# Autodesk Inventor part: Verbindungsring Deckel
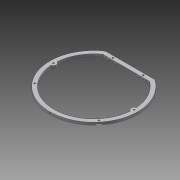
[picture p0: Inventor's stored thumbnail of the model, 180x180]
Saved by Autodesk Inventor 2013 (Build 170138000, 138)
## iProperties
Created: 2012-10
Part Number: Verbindungsring Deckel
Material: Aluminium 6061
Document SubType Name: Modeling
Designer: rYan
Density: 2.71 g/cm^3
Mass: 54.831 g
Surface Area: 139.215 cm^2
Volume: 20.2328 cm^3
Author: rYan
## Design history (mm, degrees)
sketch "Skizze1"
  geometry: L1 (0, 103.8)-(0, -118.8) reference; L2 (-121.8, 0)-(121.8, 0) reference; L3 (-48.836, 72)-(-32.512, 72); L4 (32.512, 72)-(48.836, 72); L5 (-46.314, 64)-(46.314, 64); L6 (-32.512, 72)-(32.512, 72); A1 r 87 centre (0, 0) between (-48.836, 72) and (48.836, 72); A2 r 6 centre (-80, 0) between (-78.781, -5.875) and (-78.781, 5.875); A3 r 6 centre (80, 0) between (78.781, 5.875) and (78.781, -5.875); A4 r 79 centre (0, 0) between (-46.314, 64) and (-78.781, 5.875); A5 r 79 centre (0, 0) between (-78.781, -5.875) and (78.781, -5.875); A6 r 79 centre (0, 0) between (78.781, 5.875) and (46.314, 64); 1 further point
  constraints: 12 point on circle, 8 end point, 6 centre point, 4 parallel, 2 coincident, 2 point on line, 1 symmetric about line
  dimensions: "d0" = 174 diameter of A1; "d4" = 64 distance between parallel lines of L2 L5; "d5" = 8 distance between parallel lines of L6 L5; "d98" = 12 diameter of A2; "d99" = 12 diameter of A3; "d100" = 160 distance of A3.centre A2.centre
extrude "Extrusion1" new body sketch "Skizze1" stored distance "d6" = 5; taper "d7" = 0 deg
workplane "Arbeitsebene6"
workaxis "Arbeitsachse2"
sketch "Skizze10"
  geometry: L1 (-46.314, 64)-(46.314, 64) reference; L2 (48.836, 72)-(-48.836, 72) reference; L3 (0, 0)-(-63.582, -53.351); L4 (0, 0)-(63.582, -53.351); L5 (-121.8, 0)-(121.8, 0) reference; L6 (0, 72)-(0, 64); L7 (-30, 68)-(30, 68); A1 r 87 centre (0, 0) between (-48.836, 72) and (48.836, 72) reference; A2 r 83 centre (0, 0) between (-63.582, -53.351) and (63.582, -53.351); 5 further points
  constraints: 8 end point, 5 coincident, 4 midpoint, 2 point on circle, 1 centre point, 1 perpendicular, 1 symmetric about line
  dimensions: "d77" = 166 diameter of A2; "d78" = 40 deg angle of L3 L5; "d80" = 40 deg angle of L5 L4 (= d78); "d82" = 60 distance of L7.start L7.end
hole "Bohrung6" sketch "Skizze10" at (-63.582, -53.351), (63.582, -53.351), (-30, 68), (30, 68) diameter "d83" = 3.2; stored, may be unused: countersink angle "d87" = 90 deg, drill point angle "d89" = 118 deg; dims "d84" = 6, "d85" = 4, "d86" = 2, "d88" = 8
sketch "Skizze5"
  geometry: 2 further points
  constraints: 1 coincident
hole "Bohrung2" sketch "Skizze5" at (0, 0) diameter "d21" = 2.459; stored, may be unused: countersink angle "d25" = 90 deg, drill point angle "d27" = 118 deg; dims "d22" = 6, "d23" = 4, "d24" = 2, "d26" = 8
pattern_circular "Runde Anordnung2" dims angle "d29" = -45 deg
pattern_circular "Runde Anordnung3" dims angle "d32" = 45 deg
mirror "Spiegeln1"
sketch "Skizze6"
  geometry: L1 (0, 5)-(97.673, 5) reference; L2 (8.836, 2.5)-(88.836, 2.5); L3 (48.836, 6)-(48.836, -1) reference; 3 further points
  constraints: 2 coincident, 2 end point, 1 midpoint, 1 parallel, 1 symmetric about line
  dimensions: "d34" = 80 distance of L2.start L2.end
hole "Bohrung3" sketch "Skizze6" at (8.836, 2.5), (88.836, 2.5) diameter "d36" = 2.459; stored, may be unused: countersink angle "d40" = 90 deg, drill point angle "d42" = 118 deg; dims "d37" = 6, "d38" = 4, "d39" = 2, "d41" = 8
fillet "Rundung1" dims "d90" = 2
sketch "Skizze11"
  geometry: L1 (0, 0)-(-63.582, -53.351); L2 (0, 0)-(63.582, -53.351); L3 (-63.61, -46.848)-(-79.818, -60.449); L4 (-79.818, -60.449)-(-73.391, -68.109); L5 (-73.391, -68.109)-(-57.182, -54.509); L6 (-63.61, -46.848)-(-57.182, -54.509); L7 (57.182, -54.509)-(73.391, -68.109); L8 (73.391, -68.109)-(79.818, -60.449); L9 (79.818, -60.449)-(63.61, -46.848); L10 (57.182, -54.509)-(63.61, -46.848); L11 (-45.662, 64)-(45.662, 64) reference; L12 (48.836, 72)-(-48.836, 72) reference; L13 (-30, 72)-(-30, 64); L14 (30, 72)-(30, 64); L15 (-35, 72)-(-25, 72); L16 (-25, 72)-(-25, 64); L17 (-25, 64)-(-35, 64); L18 (-35, 64)-(-35, 72); L19 (25, 72)-(35, 72); L20 (35, 72)-(35, 64); L21 (35, 64)-(25, 64); L22 (25, 64)-(25, 72); C1 r 1.6 at (-30, 68) reference; C2 r 1.6 at (30, 68) reference; C3 r 1.6 at (63.582, -53.351) reference; C4 r 1.6 at (-63.582, -53.351) reference; C5 r 100 at (0, 0); A1 r 79 centre (0, 0) between (78.781, 5.875) and (46.848, 63.61) reference; A2 r 87 centre (0, 0) between (-48.836, 72) and (48.836, 72) reference; 2 further points
  constraints: 40 end point, 9 parallel, 8 point on line, 7 perpendicular, 4 point on circle, 2 horizontal, 2 midpoint, 2 tangent, 1 centre point, 1 coincident, 2 other
  dimensions: "d91" = 200 diameter of C5; "d92" = 10 distance between parallel lines of L5 L3; "d93" = 10 distance between parallel lines of L7 L9; "d94" = 10 distance between parallel lines of L16 L18; "d95" = 10 distance between parallel lines of L20 L22
extrude "Extrusion3" cut sketch "Skizze11" distance "d96" = 2; taper "d97" = 0 deg
sketch "Skizze12"
  geometry: A1 r 6 centre (-80, 0) between (-78.781, -5.875) and (-78.781, 5.875) reference; A2 r 6 centre (80, 0) between (78.781, 5.875) and (78.781, -5.875) reference; 1 further point
hole "Bohrung7" sketch "Skizze12" at (-80, 0), (80, 0) diameter "d101" = 3.2; stored, may be unused: countersink angle "d105" = 90 deg, drill point angle "d107" = 118 deg; dims "d102" = 6, "d103" = 4, "d104" = 2, "d106" = 8
fillet "Rundung2" dims "d108" = 2
sketch "Skizze13"
  geometry: L1 (-25, 72)-(-25, 64) reference; L2 (-25, 64)-(25, 64) reference; L3 (25, 64)-(25, 72) reference; L4 (25, 72)-(-25, 72) reference; L5 (-20, 72)-(20, 72); L6 (20, 72)-(20, 64); L7 (20, 64)-(-20, 64); L8 (-20, 64)-(-20, 72); L9 (0, -118.8)-(0, 103.8) reference; 1 further point
  constraints: 8 end point, 2 parallel, 2 point on line, 1 horizontal, 1 perpendicular, 1 other
  dimensions: "d109" = 40 distance between parallel lines of L6 L8
extrude "Extrusion4" cut sketch "Skizze13" distance "d111" = 3; taper "d112" = 0 deg
workplane "Arbeitsebene7"
sketch "Skizze14"
  geometry: 2 further points
  constraints: 1 coincident
hole "Bohrung8" sketch "Skizze14" at (0, 0) diameter "d113" = 2.459; stored, may be unused: countersink angle "d117" = 90 deg, drill point angle "d119" = 118 deg; dims "d114" = 6, "d115" = 4, "d116" = 2, "d118" = 8
node "Volumenkörper1"
node "Projizierte Kontur1"
other parameters: "d2" = 8, "d3" = 72
